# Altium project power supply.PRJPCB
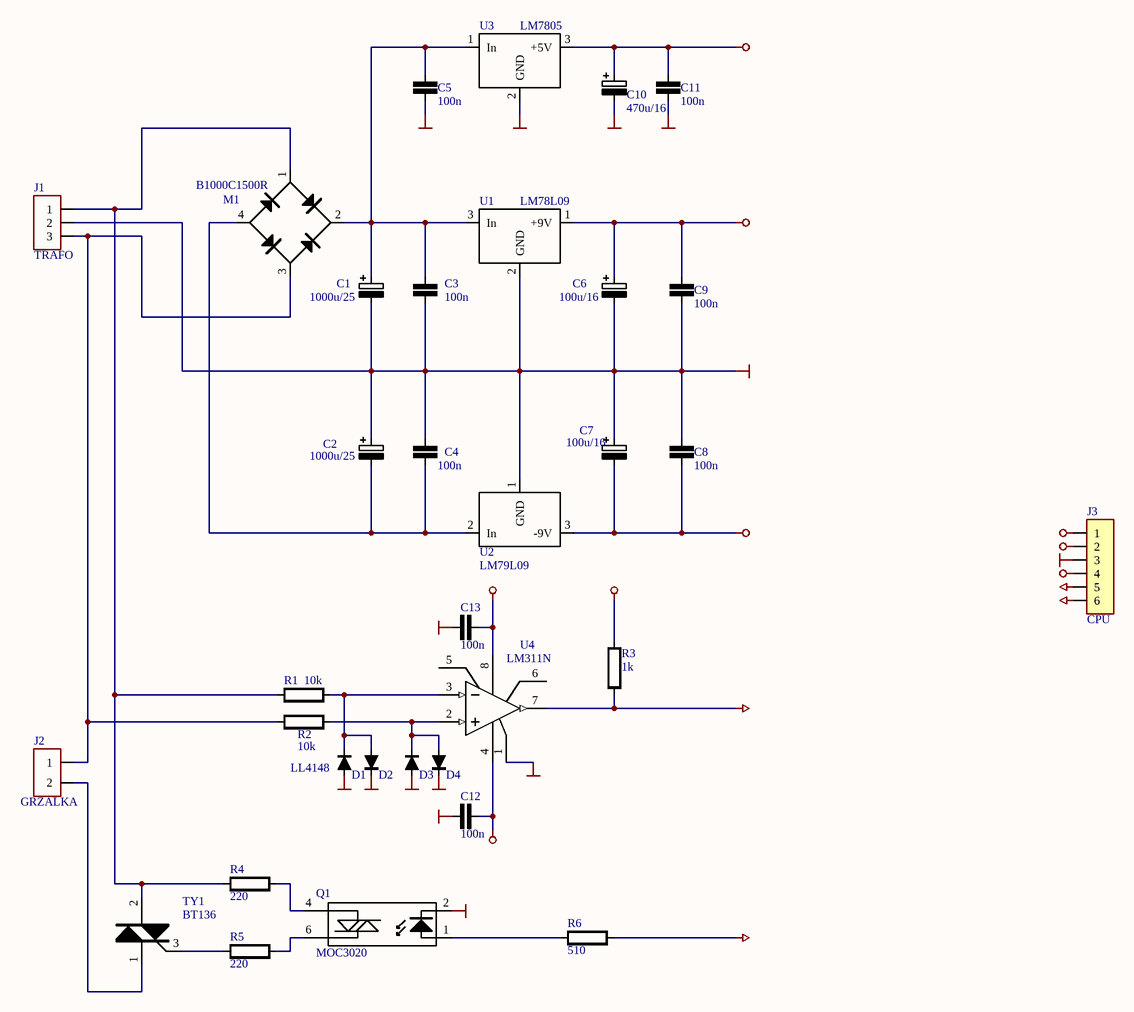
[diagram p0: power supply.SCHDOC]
1 sheet, 33 parts. Net scope: global (net labels, ports and power ports of the same name join across sheets).
Board file: power supply.PCBDOC

## Sheet power supply.SCHDOC
size B

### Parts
C1  1000u/25  [CE10]
C2  1000u/25  [CE10]
C3  100n  [1206]
C4  100n  [1206]
C5  100n  [1206]
C6  100u/16  [CE6]
C7  100u/16  [CE6]
C8  100n  [1206]
C9  100n  [1206]
C10  470u/16  [CE8]
C11  100n  [1206]
C12  100n  [1206]
C13  100n  [1206]
D1  LL4148  [MMELF]
D2  LL4148  [MMELF]  (value not drawn)
D3  LL4148  [MMELF]  (value not drawn)
D4  LL4148  [MMELF]  (value not drawn)
J1  TRAFO  [ARK3]
J2  GRZALKA  [ARK2]
J3  CPU  [ZL6A]
M1  B1000C1500R  [MOSTEK1]
Q1  MOC3020  [U6]
R1  10k  [1206]
R2  10k  [1206]
R3  1k  [1206]
R4  220  [1206]
R5  220  [1206]
R6  510  [1206]
TY1  BT136  [TYRYSTOR]
U1  LM78L09  [T]
U2  LM79L09  [T]
U3  LM7805  [TO220N]
U4  LM311N  [SO-G8]

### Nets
GND: C1.2 C2.1 C3.2 C4.1 C5.2 C6.2 C7.1 C8.1 C9.2 C10.2 C11.2 C12.2 C13.2 D1.1(A) D2.2(K) D3.1(A) D4.2(K) J1.2 J3.3 Q1.2(K) U1.2(GND) U2.1(GND) U3.2(GND) U4.1(GND)
GRZ: J3.6 R6.2
M9V: C7.2 C8.2 C12.1 J3.1 U2.3(-9V) U4.4(V-)
P9V: C6.1 C9.1 C13.1 J3.2 U1.1(+9V) U4.8(V+)
Vcc: C10.1 C11.1 J3.4 R3.2 U3.3(+5V)
ZCD: J3.5 R3.1 U4.7(OUT)
NetC1_1: C1.1 C3.1 C5.1 M1.2(V+) U1.3(In) U3.1(In)
NetC2_2: C2.2 C4.2 M1.4(V-) U2.2(In)
NetD1_2: D1.2(K) D2.1(A) R1.2 U4.3(IN-)
NetD3_2: D3.2(K) D4.1(A) R2.2 U4.2(IN+)
NetJ1_1: J1.1 M1.1(AC) R1.1 R4.1 TY1.2(A2)
NetJ1_3: J1.3 J2.1 M1.3(AC) R2.1
NetJ2_2: J2.2 TY1.1(A1)
NetQ1_1: Q1.1(A) R6.1
NetQ1_4: Q1.4(A/K) R4.2
NetQ1_6: Q1.6(A/K) R5.2
NetR5_1: R5.1 TY1.3(G)

Not connected (* = marked no-connect by the designer): U4 5(BAL) 6(BAL/STB)

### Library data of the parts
C1 C2 C6 C7 C10 = EL: Elektrolit
C3-C5 C8 C9 C11-C13 = C: Kondensator
D1-D4 = 1N4148: Dioda
J1 = ARK3: Z彻cze ARK2
J2 = ARK2: Z彻cze ARK2
J3 = CON6: Z彻cze 6
M1 = MOSTEK: Diode Bridge
Q1 = MOC3020: Optotriak
R1-R6 = R: Rezystor
TY1 = BT136: Triak
U1 = LM78L09: stabilizator
U2 = LM79L09: stabilizator
U3 = LM7805: stabilizator
U4 = LM311N: High-Performance Voltage Comparator; Manufacturer: Motorola; Class I: Analog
